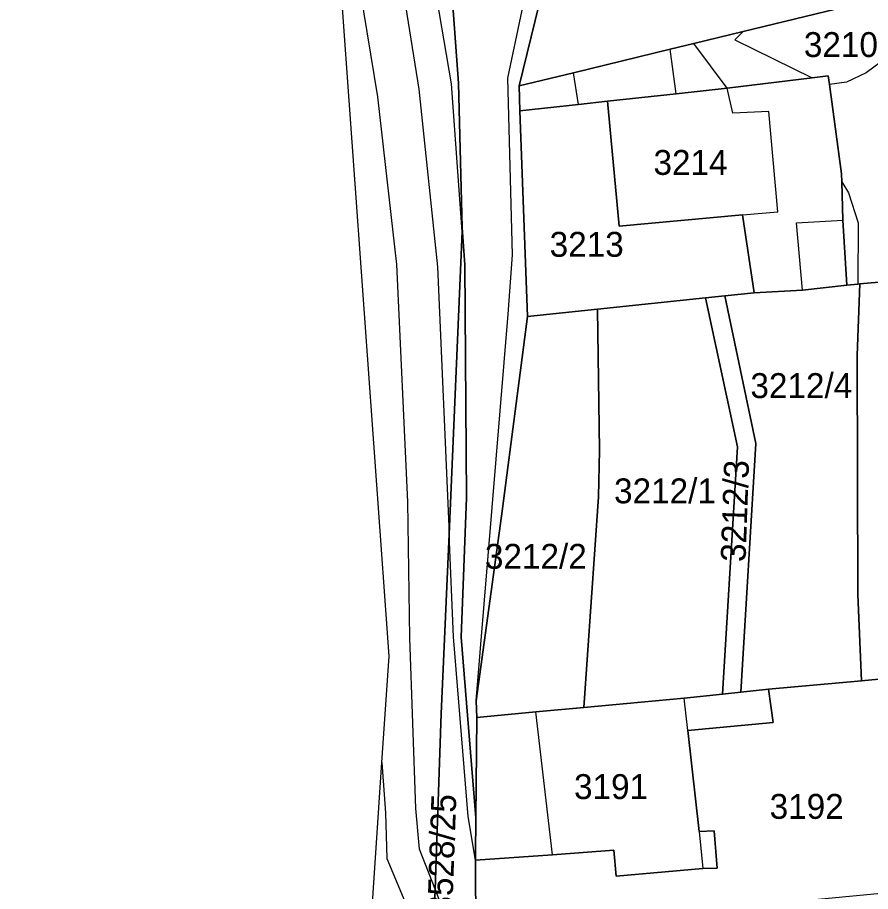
# Model space of a CAD drawing. Extents: x -262657 to -261595, y -1238015 to -1237156.
# Drawn here: x -262023.1 to -261954.5, y -1237897.4 to -1237827.1 of the extents above; entities that cross this region are included whole.
import ezdxf

# ---------------------------------------------------------------- set-up
doc = ezdxf.new("R2010")
doc.units = 0
for name, color, linetype in [('body_kn', 7, 'Continuous'), ('kladpar_druhypozemkov', 7, 'Continuous'), ('kladpar_hranice', 7, 'Continuous'), ('kladpar_parcelnecisla', 7, 'Continuous'), ('kladpar_plochy', 7, 'Continuous'), ('zappar_hrandruhpozemk', 7, 'Continuous')]:
    doc.layers.add(name, color=color, linetype=linetype)

msp = doc.modelspace()

# ---------------------------------------------------------------- linework, layer by layer
at = {"layer": 'body_kn'}
for p, q in [((-261964.78, -1237828.28), (-261964.78, -1237828.28)), ((-261964.78, -1237828.28), (-261964.78, -1237828.28)), ((-261968.75, -1237829.24), (-261968.75, -1237829.24)), ((-261965.46, -1237828.95), (-261965.46, -1237828.95)), ((-261970.64, -1237829.7), (-261970.64, -1237829.7)), ((-261983.69, -1237832.03), (-261983.69, -1237832.03)), ((-261978.42, -1237831.59), (-261978.42, -1237831.59)), ((-261959.24, -1237831.99), (-261959.24, -1237831.99)), ((-261957.94, -1237831.83), (-261957.94, -1237831.83)), ((-261954.89, -1237831.59), (-261954.89, -1237831.59)), ((-261990.83, -1237832.9), (-261990.83, -1237832.9)), ((-261988.2, -1237832.48), (-261988.2, -1237832.48)), ((-261987.64, -1237832.42), (-261987.64, -1237832.42)), ((-261982.76, -1237832.64), (-261982.76, -1237832.64)), ((-261982.76, -1237832.64), (-261982.76, -1237832.64)), ((-261966.06, -1237832.82), (-261966.06, -1237832.82)), ((-261957.84, -1237832.53), (-261957.84, -1237832.53)), ((-261956.49, -1237832.34), (-261956.49, -1237832.34)), ((-261994.12, -1237833.53), (-261994.12, -1237833.53)), ((-261970.15, -1237833.27), (-261970.15, -1237833.27)), ((-261970.15, -1237833.27), (-261970.15, -1237833.27)), ((-261978.01, -1237834.13), (-261978.01, -1237834.13)), ((-261978.01, -1237834.13), (-261978.01, -1237834.13)), ((-261975.67, -1237833.87), (-261975.67, -1237833.87)), ((-261975.67, -1237833.87), (-261975.67, -1237833.87)), ((-261982.71, -1237834.64), (-261982.71, -1237834.64)), ((-261982.71, -1237834.64), (-261982.71, -1237834.64)), ((-261965.61, -1237834.82), (-261965.61, -1237834.82)), ((-261962.71, -1237834.69), (-261962.71, -1237834.69)), ((-261956.87, -1237839.7), (-261956.87, -1237839.7)), ((-261956.85, -1237840.34), (-261956.85, -1237840.34)), ((-261956.85, -1237840.34), (-261956.85, -1237840.34)), ((-261956.31, -1237841.22), (-261956.31, -1237841.22)), ((-261964.82, -1237842.99), (-261964.82, -1237842.99)), ((-261964.82, -1237842.99), (-261964.82, -1237842.99)), ((-261961.99, -1237842.77), (-261961.99, -1237842.77)), ((-261956.78, -1237843.42), (-261956.78, -1237843.42)), ((-261956.78, -1237843.42), (-261956.78, -1237843.42)), ((-261987.36, -1237844.03), (-261987.36, -1237844.03)), ((-261987.36, -1237844.03), (-261987.36, -1237844.03)), ((-261974.74, -1237843.92), (-261974.74, -1237843.92)), ((-261960.5, -1237843.64), (-261960.5, -1237843.64)), ((-261955.54, -1237843.64), (-261955.54, -1237843.64)), ((-261987.35, -1237844.34), (-261987.35, -1237844.34)), ((-261987.35, -1237844.34), (-261987.35, -1237844.34)), ((-261983.3, -1237846.2), (-261983.3, -1237846.2)), ((-261992.61, -1237846.99), (-261992.61, -1237846.99)), ((-261989.32, -1237847.18), (-261989.32, -1237847.18)), ((-261987.14, -1237847.02), (-261987.14, -1237847.02)), ((-261960.01, -1237849.06), (-261960.01, -1237849.06)), ((-261960.01, -1237849.06), (-261960.01, -1237849.06)), ((-261956.45, -1237848.64), (-261956.45, -1237848.64)), ((-261955.56, -1237848.56), (-261955.56, -1237848.56)), ((-261955.42, -1237848.55), (-261955.42, -1237848.55)), ((-261967.8, -1237849.66), (-261967.8, -1237849.66)), ((-261967.8, -1237849.66), (-261967.8, -1237849.66)), ((-261966.24, -1237849.5), (-261966.24, -1237849.5)), ((-261963.9, -1237849.26), (-261963.9, -1237849.26)), ((-261963.9, -1237849.26), (-261963.9, -1237849.26)), ((-261983.66, -1237850.99), (-261983.66, -1237850.99)), ((-261982.1, -1237851.16), (-261982.1, -1237851.16)), ((-261982.1, -1237851.16), (-261982.1, -1237851.16)), ((-261976.49, -1237850.57), (-261976.49, -1237850.57)), ((-261976.49, -1237850.57), (-261976.49, -1237850.57)), ((-261955.63, -1237854.3), (-261955.63, -1237854.3)), ((-261965.23, -1237861.64), (-261965.23, -1237861.64)), ((-261965.23, -1237861.64), (-261965.23, -1237861.64)), ((-261963.77, -1237861.38), (-261963.77, -1237861.38)), ((-261976.31, -1237861.92), (-261976.31, -1237861.92)), ((-261987.01, -1237865.75), (-261987.01, -1237865.75)), ((-261976.4, -1237865.67), (-261976.4, -1237865.67)), ((-261991.71, -1237866.06), (-261991.71, -1237866.06)), ((-261984.19, -1237867.22), (-261984.19, -1237867.22)), ((-261988.4, -1237868.65), (-261988.4, -1237868.65)), ((-261955.57, -1237873.5), (-261955.57, -1237873.5)), ((-261991.55, -1237876.99), (-261991.55, -1237876.99)), ((-261988.04, -1237876.9), (-261988.04, -1237876.9)), ((-261987.42, -1237876.92), (-261987.42, -1237876.92)), ((-261993.22, -1237878.45), (-261993.22, -1237878.45)), ((-261955.27, -1237880.43), (-261955.27, -1237880.43)), ((-261964.96, -1237881.34), (-261964.96, -1237881.34)), ((-261962.75, -1237881.1), (-261962.75, -1237881.1)), ((-261986.22, -1237882.06), (-261986.22, -1237882.06)), ((-261986.22, -1237882.06), (-261986.22, -1237882.06)), ((-261969.51, -1237881.84), (-261969.51, -1237881.84)), ((-261966.44, -1237881.5), (-261966.44, -1237881.5)), ((-261977.57, -1237882.58), (-261977.57, -1237882.58)), ((-261989.03, -1237883.09), (-261989.03, -1237883.09)), ((-261986.16, -1237883.39), (-261986.16, -1237883.39)), ((-261981.43, -1237882.94), (-261981.43, -1237882.94)), ((-261962.37, -1237883.78), (-261962.37, -1237883.78)), ((-261969.22, -1237884.42), (-261969.22, -1237884.42)), ((-261969.22, -1237884.42), (-261969.22, -1237884.42)), ((-261993.79, -1237887.01), (-261993.79, -1237887.01)), ((-261993.79, -1237887.01), (-261993.79, -1237887.01)), ((-261993.51, -1237891.06), (-261993.51, -1237891.06)), ((-261991.08, -1237890.69), (-261991.08, -1237890.69)), ((-261986.88, -1237891.35), (-261986.88, -1237891.35)), ((-261986.24, -1237891.44), (-261986.24, -1237891.44)), ((-261968.3, -1237892.56), (-261968.3, -1237892.56)), ((-261968.3, -1237892.56), (-261968.3, -1237892.56)), ((-261967.1, -1237892.49), (-261967.1, -1237892.49)), ((-261990.78, -1237893.98), (-261990.78, -1237893.98)), ((-261993.41, -1237894.73), (-261993.41, -1237894.73)), ((-261986.27, -1237894.41), (-261986.27, -1237894.41)), ((-261980.09, -1237894.42), (-261980.09, -1237894.42)), ((-261980.09, -1237894.42), (-261980.09, -1237894.42)), ((-261975.16, -1237894.06), (-261975.16, -1237894.06)), ((-261986.27, -1237894.84), (-261986.27, -1237894.84)), ((-261986.27, -1237894.84), (-261986.27, -1237894.84)), ((-261974.99, -1237896.13), (-261974.99, -1237896.13)), ((-261968.03, -1237895.52), (-261968.03, -1237895.52)), ((-261966.86, -1237895.49), (-261966.86, -1237895.49)), ((-261989.52, -1237897.17), (-261989.52, -1237897.17)), ((-261989.52, -1237897.17), (-261989.52, -1237897.17))]:
    msp.add_line(p, q, dxfattribs=at)
at = {"layer": 'kladpar_druhypozemkov'}
for p, q in [((-261955.84, -1237828.67), (-261955.84, -1237828.67)), ((-261969.01, -1237837.51), (-261969.01, -1237837.51)), ((-261977.69, -1237844.77), (-261977.69, -1237844.77)), ((-261959.75, -1237855.71), (-261959.75, -1237855.71)), ((-261964.3, -1237861.91), (-261964.3, -1237861.91)), ((-261970.84, -1237864.54), (-261970.84, -1237864.54)), ((-261980.48, -1237869.24), (-261980.48, -1237869.24)), ((-261976.15, -1237887.63), (-261976.15, -1237887.63)), ((-261959.38, -1237889.64), (-261959.38, -1237889.64))]:
    msp.add_line(p, q, dxfattribs=at)
at = {"layer": 'kladpar_hranice'}
for p, q in [((-261982.71, -1237834.64), (-261982.76, -1237832.64)), ((-261982.1, -1237851.16), (-261982.71, -1237834.64))]:
    msp.add_line(p, q, dxfattribs=at)
for points in [[(-261981.16, -1237826.07), (-261982.76, -1237832.64), (-261982.71, -1237834.64), (-261982.1, -1237851.16), (-261984.19, -1237867.22), (-261986.22, -1237882.06), (-261986.16, -1237883.39), (-261986.24, -1237891.44), (-261987.42, -1237876.92), (-261987.01, -1237865.75), (-261987.14, -1237847.02), (-261987.36, -1237844.03), (-261987.64, -1237832.42), (-261990.1, -1237798.73), (-261994.21, -1237771.78), (-261997.77, -1237753.43), (-262005, -1237725.87)], [(-262005, -1237725.87), (-261997.77, -1237753.43), (-261994.21, -1237771.78), (-261990.1, -1237798.73), (-261987.64, -1237832.42), (-261987.36, -1237844.03), (-261987.35, -1237844.34), (-261988.4, -1237868.65), (-261989.03, -1237883.09), (-261989.52, -1237897.17), (-261989.7, -1237902.51)], [(-261996.13, -1237922.1), (-261993.79, -1237887.01), (-261993.22, -1237878.45), (-261997.19, -1237823.36), (-262014.71, -1237769.39), (-262020.83, -1237750.56), (-262021.16, -1237749.53), (-262023.07, -1237746.54)], [(-261982.76, -1237832.64), (-261981.16, -1237826.07), (-261974.24, -1237797.56), (-261979.29, -1237780.53), (-261926.09, -1237769.65), (-261922.63, -1237778.24), (-261927.57, -1237779.48), (-261925.24, -1237804.88), (-261924.11, -1237817.62), (-261954.82, -1237825.86), (-261964.78, -1237828.28), (-261968.75, -1237829.24), (-261970.64, -1237829.7), (-261978.42, -1237831.59), (-261982.76, -1237832.64)], [(-261982.76, -1237832.64), (-261978.42, -1237831.59), (-261970.64, -1237829.7), (-261968.75, -1237829.24), (-261964.78, -1237828.28), (-261954.82, -1237825.86), (-261924.11, -1237817.62), (-261924, -1237817.96), (-261923.89, -1237818.34), (-261923.62, -1237819.21), (-261923.36, -1237820.86), (-261923.35, -1237820.94), (-261923.32, -1237821.16), (-261928.12, -1237822.84), (-261934.7, -1237824.83), (-261946.81, -1237828.25), (-261946.74, -1237828.94), (-261946.3, -1237833.58), (-261946.1, -1237835.46), (-261947.91, -1237862.67), (-261948.53, -1237879.67), (-261949.09, -1237879.78)], [(-261966.06, -1237832.82), (-261959.24, -1237831.99), (-261957.94, -1237831.83), (-261957.84, -1237832.53), (-261956.87, -1237839.7), (-261956.85, -1237840.34), (-261956.78, -1237843.42)], [(-261956.78, -1237843.42), (-261956.85, -1237840.34), (-261956.87, -1237839.7), (-261957.84, -1237832.53), (-261957.94, -1237831.83), (-261959.24, -1237831.99), (-261966.06, -1237832.82)], [(-261963.9, -1237849.26), (-261964.82, -1237842.99), (-261974.74, -1237843.92), (-261975.67, -1237833.87), (-261970.15, -1237833.27), (-261966.06, -1237832.82)], [(-261966.06, -1237832.82), (-261970.15, -1237833.27), (-261975.67, -1237833.87)], [(-261982.71, -1237834.64), (-261978.01, -1237834.13), (-261975.67, -1237833.87)], [(-261975.67, -1237833.87), (-261978.01, -1237834.13), (-261982.71, -1237834.64)], [(-261975.67, -1237833.87), (-261974.74, -1237843.92), (-261964.82, -1237842.99), (-261963.9, -1237849.26), (-261966.24, -1237849.5), (-261967.8, -1237849.66), (-261976.49, -1237850.57), (-261982.1, -1237851.16)], [(-261956.78, -1237843.42), (-261956.45, -1237848.64), (-261960.01, -1237849.06), (-261963.9, -1237849.26)], [(-261952.65, -1237848.3), (-261955.42, -1237848.55), (-261955.56, -1237848.56), (-261956.45, -1237848.64), (-261956.78, -1237843.42)], [(-261987.36, -1237844.03), (-261987.14, -1237847.02), (-261987.01, -1237865.75), (-261987.42, -1237876.92), (-261986.24, -1237891.44), (-261986.27, -1237894.41), (-261986.27, -1237894.84), (-261986.26, -1237900.61), (-261986.29, -1237902.6), (-261986.33, -1237905.88), (-261987.65, -1237906.07), (-261989.7, -1237902.51), (-261989.52, -1237897.17), (-261989.03, -1237883.09), (-261988.4, -1237868.65), (-261987.35, -1237844.34), (-261987.36, -1237844.03)], [(-261950.71, -1237897.26), (-261952.76, -1237880.2), (-261955.27, -1237880.43), (-261955.57, -1237873.5), (-261955.63, -1237854.3), (-261955.42, -1237848.55), (-261952.65, -1237848.3)], [(-261960.01, -1237849.06), (-261956.45, -1237848.64), (-261955.56, -1237848.56), (-261955.42, -1237848.55), (-261955.63, -1237854.3), (-261955.57, -1237873.5), (-261955.27, -1237880.43), (-261962.75, -1237881.1), (-261964.96, -1237881.34), (-261963.77, -1237861.38), (-261966.24, -1237849.5), (-261963.9, -1237849.26), (-261960.01, -1237849.06)], [(-261967.8, -1237849.66), (-261965.23, -1237861.64), (-261966.44, -1237881.5), (-261969.51, -1237881.84), (-261977.57, -1237882.58), (-261976.4, -1237865.67), (-261976.31, -1237861.92), (-261976.49, -1237850.57), (-261967.8, -1237849.66)], [(-261965.23, -1237861.64), (-261967.8, -1237849.66), (-261966.24, -1237849.5), (-261963.77, -1237861.38), (-261964.96, -1237881.34), (-261966.44, -1237881.5), (-261965.23, -1237861.64)], [(-261976.49, -1237850.57), (-261976.31, -1237861.92), (-261976.4, -1237865.67), (-261977.57, -1237882.58), (-261981.43, -1237882.94), (-261986.16, -1237883.39), (-261986.22, -1237882.06), (-261984.19, -1237867.22), (-261982.1, -1237851.16), (-261976.49, -1237850.57)], [(-261986.26, -1237900.61), (-261986.27, -1237894.84), (-261980.09, -1237894.42), (-261975.16, -1237894.06), (-261974.99, -1237896.13), (-261968.03, -1237895.52), (-261966.86, -1237895.49), (-261967.1, -1237892.49), (-261968.3, -1237892.56), (-261969.22, -1237884.42), (-261962.37, -1237883.78), (-261962.75, -1237881.1), (-261955.27, -1237880.43), (-261952.76, -1237880.2), (-261950.71, -1237897.26), (-261953.72, -1237897.54), (-261968, -1237898.89), (-261969.6, -1237899.04), (-261981.07, -1237900.12), (-261983.15, -1237900.32), (-261986.26, -1237900.61)], [(-261986.27, -1237894.84), (-261986.27, -1237894.41), (-261986.24, -1237891.44), (-261986.16, -1237883.39), (-261981.43, -1237882.94), (-261977.57, -1237882.58), (-261969.51, -1237881.84), (-261966.44, -1237881.5), (-261964.96, -1237881.34), (-261962.75, -1237881.1), (-261962.37, -1237883.78), (-261969.22, -1237884.42), (-261968.3, -1237892.56), (-261967.1, -1237892.49), (-261966.86, -1237895.49), (-261968.03, -1237895.52), (-261974.99, -1237896.13), (-261975.16, -1237894.06), (-261980.09, -1237894.42), (-261986.27, -1237894.84)]]:
    msp.add_lwpolyline(points, dxfattribs=at)
at = {"layer": 'kladpar_plochy'}
for points in [[(-261995.45, -1237734.05), (-261989.56, -1237771.61), (-261981.69, -1237822.6), (-261981.16, -1237826.07), (-261982.76, -1237832.64), (-261982.71, -1237834.64), (-261982.1, -1237851.16), (-261984.19, -1237867.22), (-261986.22, -1237882.06), (-261986.16, -1237883.39), (-261986.24, -1237891.44), (-261987.42, -1237876.92), (-261987.01, -1237865.75), (-261987.14, -1237847.02), (-261987.36, -1237844.03), (-261987.64, -1237832.42), (-261990.1, -1237798.73), (-261994.21, -1237771.78), (-261997.77, -1237753.43), (-262005, -1237725.87)], [(-262005, -1237725.87), (-261997.77, -1237753.43), (-261994.21, -1237771.78), (-261990.1, -1237798.73), (-261987.64, -1237832.42), (-261987.36, -1237844.03), (-261987.35, -1237844.34), (-261988.4, -1237868.65), (-261989.03, -1237883.09), (-261989.52, -1237897.17), (-261989.7, -1237902.51)], [(-261996.13, -1237922.1), (-261993.79, -1237887.01), (-261993.22, -1237878.45), (-261997.19, -1237823.36), (-262014.71, -1237769.39), (-262020.83, -1237750.56), (-262021.16, -1237749.53), (-262023.07, -1237746.54)], [(-261952.65, -1237848.3), (-261955.42, -1237848.55), (-261955.56, -1237848.56), (-261956.45, -1237848.64), (-261956.78, -1237843.42), (-261956.85, -1237840.34), (-261956.87, -1237839.7), (-261957.84, -1237832.53), (-261957.94, -1237831.83), (-261959.24, -1237831.99), (-261966.06, -1237832.82), (-261970.15, -1237833.27), (-261975.67, -1237833.87), (-261978.01, -1237834.13), (-261982.71, -1237834.64), (-261982.76, -1237832.64), (-261978.42, -1237831.59), (-261970.64, -1237829.7), (-261968.75, -1237829.24), (-261964.78, -1237828.28), (-261954.82, -1237825.86), (-261924.11, -1237817.62)], [(-261953.72, -1237897.54), (-261950.71, -1237897.26), (-261952.76, -1237880.2), (-261955.27, -1237880.43), (-261955.57, -1237873.5), (-261955.63, -1237854.3), (-261955.42, -1237848.55), (-261952.65, -1237848.3), (-261950.75, -1237864.05), (-261950.86, -1237867.45), (-261950.68, -1237874.14), (-261950.25, -1237879.91), (-261950.23, -1237882.83), (-261949.03, -1237897.48)]]:
    msp.add_lwpolyline(points, dxfattribs=at)
for points in [[(-261982.76, -1237832.64), (-261981.16, -1237826.07), (-261974.24, -1237797.56), (-261979.29, -1237780.53), (-261926.09, -1237769.65), (-261922.63, -1237778.24), (-261927.57, -1237779.48), (-261925.24, -1237804.88), (-261924.11, -1237817.62), (-261954.82, -1237825.86), (-261964.78, -1237828.28), (-261968.75, -1237829.24), (-261970.64, -1237829.7), (-261978.42, -1237831.59)], [(-261963.9, -1237849.26), (-261964.82, -1237842.99), (-261974.74, -1237843.92), (-261975.67, -1237833.87), (-261970.15, -1237833.27), (-261966.06, -1237832.82), (-261959.24, -1237831.99), (-261957.94, -1237831.83), (-261957.84, -1237832.53), (-261956.87, -1237839.7), (-261956.85, -1237840.34), (-261956.78, -1237843.42), (-261956.45, -1237848.64), (-261960.01, -1237849.06)], [(-261982.1, -1237851.16), (-261982.71, -1237834.64), (-261978.01, -1237834.13), (-261975.67, -1237833.87), (-261974.74, -1237843.92), (-261964.82, -1237842.99), (-261963.9, -1237849.26), (-261966.24, -1237849.5), (-261967.8, -1237849.66), (-261976.49, -1237850.57)], [(-261987.36, -1237844.03), (-261987.14, -1237847.02), (-261987.01, -1237865.75), (-261987.42, -1237876.92), (-261986.24, -1237891.44), (-261986.27, -1237894.41), (-261986.27, -1237894.84), (-261986.26, -1237900.61), (-261986.29, -1237902.6), (-261986.33, -1237905.88), (-261987.65, -1237906.07), (-261989.7, -1237902.51), (-261989.52, -1237897.17), (-261989.03, -1237883.09), (-261988.4, -1237868.65), (-261987.35, -1237844.34)], [(-261960.01, -1237849.06), (-261956.45, -1237848.64), (-261955.56, -1237848.56), (-261955.42, -1237848.55), (-261955.63, -1237854.3), (-261955.57, -1237873.5), (-261955.27, -1237880.43), (-261962.75, -1237881.1), (-261964.96, -1237881.34), (-261963.77, -1237861.38), (-261966.24, -1237849.5), (-261963.9, -1237849.26)], [(-261967.8, -1237849.66), (-261965.23, -1237861.64), (-261966.44, -1237881.5), (-261969.51, -1237881.84), (-261977.57, -1237882.58), (-261976.4, -1237865.67), (-261976.31, -1237861.92), (-261976.49, -1237850.57)], [(-261965.23, -1237861.64), (-261967.8, -1237849.66), (-261966.24, -1237849.5), (-261963.77, -1237861.38), (-261964.96, -1237881.34), (-261966.44, -1237881.5)], [(-261976.49, -1237850.57), (-261976.31, -1237861.92), (-261976.4, -1237865.67), (-261977.57, -1237882.58), (-261981.43, -1237882.94), (-261986.16, -1237883.39), (-261986.22, -1237882.06), (-261984.19, -1237867.22), (-261982.1, -1237851.16)], [(-261986.26, -1237900.61), (-261986.27, -1237894.84), (-261980.09, -1237894.42), (-261975.16, -1237894.06), (-261974.99, -1237896.13), (-261968.03, -1237895.52), (-261966.86, -1237895.49), (-261967.1, -1237892.49), (-261968.3, -1237892.56), (-261969.22, -1237884.42), (-261962.37, -1237883.78), (-261962.75, -1237881.1), (-261955.27, -1237880.43), (-261952.76, -1237880.2), (-261950.71, -1237897.26), (-261953.72, -1237897.54), (-261968, -1237898.89), (-261969.6, -1237899.04), (-261981.07, -1237900.12), (-261983.15, -1237900.32)], [(-261986.27, -1237894.84), (-261986.27, -1237894.41), (-261986.24, -1237891.44), (-261986.16, -1237883.39), (-261981.43, -1237882.94), (-261977.57, -1237882.58), (-261969.51, -1237881.84), (-261966.44, -1237881.5), (-261964.96, -1237881.34), (-261962.75, -1237881.1), (-261962.37, -1237883.78), (-261969.22, -1237884.42), (-261968.3, -1237892.56), (-261967.1, -1237892.49), (-261966.86, -1237895.49), (-261968.03, -1237895.52), (-261974.99, -1237896.13), (-261975.16, -1237894.06), (-261980.09, -1237894.42)]]:
    msp.add_lwpolyline(points, close=True, dxfattribs=at)
at = {"layer": 'zappar_hrandruhpozemk'}
for p, q in [((-261993.04, -1237819.16), (-261990.83, -1237832.9)), ((-261966.06, -1237832.82), (-261968.75, -1237829.24)), ((-261970.15, -1237833.27), (-261970.64, -1237829.7)), ((-261953.15, -1237830.31), (-261954.89, -1237831.59)), ((-261978.01, -1237834.13), (-261978.42, -1237831.59)), ((-261961.99, -1237842.77), (-261962.71, -1237834.69)), ((-261956.85, -1237840.34), (-261956.31, -1237841.22)), ((-261964.82, -1237842.99), (-261961.99, -1237842.77)), ((-261960.5, -1237843.64), (-261956.78, -1237843.42)), ((-261960.01, -1237849.06), (-261960.5, -1237843.64)), ((-261986.22, -1237882.06), (-261983.66, -1237850.99)), ((-261991.08, -1237890.69), (-261991.55, -1237876.99)), ((-261969.22, -1237884.42), (-261969.51, -1237881.84)), ((-261980.09, -1237894.42), (-261981.43, -1237882.94)), ((-261986.27, -1237894.84), (-261986.88, -1237891.35)), ((-261968.3, -1237892.56), (-261968.03, -1237895.52)), ((-261993.41, -1237894.73), (-261991.25, -1237899.82)), ((-261989, -1237898.49), (-261989.52, -1237897.17))]:
    msp.add_line(p, q, dxfattribs=at)
for points in [[(-261991.55, -1237876.99), (-261991.71, -1237866.06), (-261992.61, -1237846.99), (-261994.12, -1237833.53), (-261996.38, -1237819.78), (-262000.61, -1237803.1), (-262003.58, -1237792.9)], [(-261987.35, -1237844.34), (-261988.2, -1237832.48), (-261990.57, -1237818.63), (-261990.68, -1237810.4), (-261991.11, -1237800.3), (-261992.75, -1237810.51), (-261993.04, -1237819.16)], [(-261983.66, -1237850.99), (-261983.3, -1237846.2), (-261983.69, -1237832.03), (-261981.69, -1237822.6)], [(-261964.78, -1237828.28), (-261965.46, -1237828.95), (-261959.24, -1237831.99)], [(-261954.89, -1237831.59), (-261956.49, -1237832.34), (-261957.84, -1237832.53)], [(-261990.83, -1237832.9), (-261989.32, -1237847.18), (-261988.4, -1237868.65)], [(-261962.71, -1237834.69), (-261965.61, -1237834.82), (-261966.06, -1237832.82)], [(-261956.31, -1237841.22), (-261955.54, -1237843.64), (-261955.56, -1237848.56)], [(-261986.88, -1237891.35), (-261988.04, -1237876.9), (-261988.4, -1237868.65)], [(-261993.79, -1237887.01), (-261993.51, -1237891.06), (-261993.41, -1237894.73)], [(-261989.52, -1237897.17), (-261990.78, -1237893.98), (-261991.08, -1237890.69)]]:
    msp.add_lwpolyline(points, dxfattribs=at)

# ---------------------------------------------------------------- texts
at = {"layer": 'kladpar_parcelnecisla'}
for s, p in [('3210/1', (-261959.902, -1237830.32)), ('3214', (-261971.98, -1237839.79)), ('3213', (-261980.322, -1237846.37)), ('3212/4', (-261964.196, -1237857.72)), ('3212/1', (-261975.147, -1237866.18)), ('3212/2', (-261985.523, -1237871.44)), ('3191', (-261978.363, -1237889.94)), ('3192', (-261962.65, -1237891.53))]:
    msp.add_text(s, height=2, dxfattribs=at).set_placement(p)
for s, p in [('3212/3', (-261964.589, -1237870.911)), ('3528/25', (-261988.153, -1237899.24))]:
    msp.add_text(s, height=2, rotation=88, dxfattribs=at).set_placement(p)

doc.saveas('drawing.dxf')
